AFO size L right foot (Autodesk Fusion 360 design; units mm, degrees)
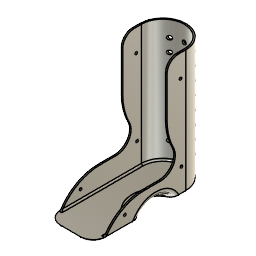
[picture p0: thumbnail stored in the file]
part number: 2025-10-02-12-56-12-317
sketch "Sketch1" plane through (0, 0, 0) normal (0, 0, 1) x axis (1, 0, 0)
  line L1 (-30.6, -123.83) -> (-30.6, 0)
  line L2 (30.6, -123.83) -> (-30.6, -123.83)
  line L3 (30.6, 0) -> (30.6, -123.83)
  line L4 (-28.6, 0) -> (-28.6, -123.83)
  line L5 (28.6, 0) -> (28.6, -123.83)
  line L6 (-28.6, 0) -> (-30.6, 0)
  line L7 (30.6, 0) -> (28.6, 0)
  line L8 (-28.6, -106.33) -> (-30.6, -106.33)
  line L9 (-13.1, -123.83) -> (-13.1, -106.33)
  line L10 (13.1, -123.83) -> (13.1, -106.33)
  line L11 (13.1, -123.83) -> (-13.1, -123.83)
  line L12 (35, -106.33) -> (-13.1252, -106.33)
  circle C1 centre (0, 0) radius 30.6
  circle C2 centre (0, 0) radius 28.6
  circle C3 centre (-13.1, -106.33) radius 17.5
  circle C4 centre (13.1, -106.33) radius 17.5
  circle C5 centre (-13.1, -106.33) radius 15.5
  circle C6 centre (13.1, -106.33) radius 15.5
  point P1 (0, 0)
  point P2 (0, 0)
  point P3 (-30.6, 0)
  point P6 (30.6, 0)
  point P7 (0, 0)
  point P8 (-28.6, 0)
  point P10 (28.6, 0)
  point P11 (28.6, -123.83)
  point P9 (-28.6, -123.83)
  point P16 (-30.6, -106.33)
  point P17 (-28.6, -106.33)
  point P12 (-13.1, -106.33)
  point P18 (-13.1, -106.33)
  point P19 (-13.1, -123.83)
  point P15 (13.1, -106.33)
  point P20 (13.1, -106.33)
  point P21 (13.1, -123.83)
  point P13 (13.1, -106.33)
  coincident P1 P2
  coincident C1 P3
  tangent C1 L1
  vertical L1
  perpendicular L1 L2
  coincident C1 P6
  tangent C1 L3
  perpendicular L2 L3
  coincident P1 P7
  vertical L4
  coincident C2 P8
  vertical L5
  coincident C2 P10
  perpendicular L4 L6
  perpendicular L3 L7
  coincident L2 P11
  coincident L2 P9
  tangent L3 C4
  tangent L1 C3
  tangent L2 C3
  tangent L2 C4
  concentric C3 C5
  tangent L4 C5
  concentric C4 C6
  tangent L5 C6
  coincident C3 P16
  coincident C5 P17
  coincident L4 P17
  perpendicular L4 L8
  coincident P12 P18
  coincident L2 P19
  coincident C3 P19
  perpendicular L2 L9
  coincident P15 P20
  coincident L2 P21
  coincident C4 P21
  perpendicular L2 L10
  perpendicular L3 L12
  coincident P13 L12
  dimension "d2" diameter C1 = 61.2 (= "d57 + ( 2 * 2 ) * 1 mm")
  dimension "d4" distance P2 L2 = 123.83
  dimension "d57" diameter C2 = 57.2
  dimension "d73" diameter C3 = 35
  dimension "d74" diameter C4 = 35
extrude "Extrude1" new body sketch "Sketch1" profile of C1 L1 L3 L4 L5 L6 L7 C3 C4 L8 L12 along normal blind 30
extrude "Extrude2" add sketch "Sketch1" profile of C1 C2 L4 L5 C3 C4 C5 C6 L8 L9 L10 L12 along normal blind 2
extrude "Extrude8" add sketch "Sketch1" profile of L2 C3 C4 L11 along normal blind 2
extrude "Extrude3" add sketch "Sketch1" profile of C1 C2 L6 L7 along normal blind 165.1
work_plane "WorkPlane3" AlongDistance 40
sphere_primitive "SpherePrimitive3" Diameter 55
move_face "MoveFace3"
boundary_fill "BoundaryFill2"
offset_faces "OffsetFaces3" distance 2
shell "Shell5" innerThickness 2
fillet "Fillet31" radius 25
extrude "Extrude15" cut of existing geometry blind -8
work_plane "WorkPlane1" RotateAngle -90
sketch "Sketch2" plane through (30.6, 0, 0) normal (1, 0, 0) x axis (0, 1, 0)
  line L1 (0, 165.1) -> (-25, 165.1)
  line L2 (0, 30) -> (0, 165.1)
  line L3 (-25, 75.1) -> (-25, 165.1)
  line L4 (0, 30) -> (-25, 75.1)
  circle C1 centre (-7, 135.1) radius 1.75
  point P2 (0, 30)
  point P6 (0, 30)
  point P4 (0, 165.1)
  point P7 (0, 165.1)
  point P3 (-25, 165.1)
  point P5 (-25, 75.1)
  point P8 (-7, 135.1)
  horizontal L1
  perpendicular L1 L2
  perpendicular L1 L3
  coincident P2 P6
  coincident P4 P7
  dimension "d25" distance P3 P4 = 25
  dimension "d28" distance P3 P5 = 90
  dimension "d43" diameter C1 = 3.5
  dimension "d45" distance L3 P8 = 18
  dimension "d47" distance L1 P8 = 30
extrude "Extrude11" add sketch "Sketch2" against normal blind 2
mirror "Mirror1" mirrorStitchTolerance 0.1
work_plane "WorkPlane4" AlongDistance 24.25
sketch "Sketch9" plane through (0, 24.25, 0) normal (0, 1, 0) x axis (1, 0, 0)
  circle C1 centre (0, -25) radius 2.5
  circle C2 centre (0, -42) radius 2.5
  circle C3 centre (0, -59) radius 2.5
  circle C4 centre (0, -76) radius 2.5
  circle C5 centre (0, -110) radius 2.5
  circle C6 centre (0, -93) radius 2.5
  circle C7 centre (0, -144) radius 2.5
  circle C8 centre (0, -127) radius 2.5
  point P2 (0, -25)
  point P8 (0, 0)
  point P3 (0, -42)
  point P4 (0, -59)
  point P5 (0, -76)
  point P7 (0, -93)
  point P6 (0, -110)
  point P10 (0, -127)
  point P9 (0, -144)
  dimension "d123" diameter C1 = 5
  dimension "d124" diameter C2 = 5
  dimension "d125" diameter C3 = 5
  dimension "d126" diameter C4 = 5
  dimension "d127" diameter C5 = 5
  dimension "d128" diameter C6 = 5
  dimension "d129" distance P2 P8 = 25
  dimension "d130" distance P2 P3 = 17
  dimension "d131" distance P3 P4 = 17
  dimension "d132" distance P4 P5 = 17 (= "d131")
  dimension "d133" distance P5 P7 = 17 (= "d131")
  dimension "d134" distance P6 P7 = 17 (= "d131")
  dimension "d183" diameter C7 = 5
  dimension "d184" diameter C8 = 5
  dimension "d232" distance P6 P10 = 17
  dimension "d233" distance P9 P10 = 17
extrude "Extrude12" cut sketch "Sketch9" along normal blind 70
path_pattern "PathPattern2" PathPatternDelta 89
fillet "Fillet28" radius 60
fillet "Fillet18" radius 80
fillet "Fillet32" radius 10
fillet "Fillet33" radius 10
fillet "Fillet34" radius 20
fillet "Fillet35" radius 15
fillet "Fillet36" radius 2
fillet "Fillet37" radius 4
hole "Hole3" HoleDepth 90 HoleDiameter 3.5 TipAngle 118
hole "Hole4" HoleDepth 90 HoleDiameter 3.5 TipAngle 118
fillet "Fillet44" radius 2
